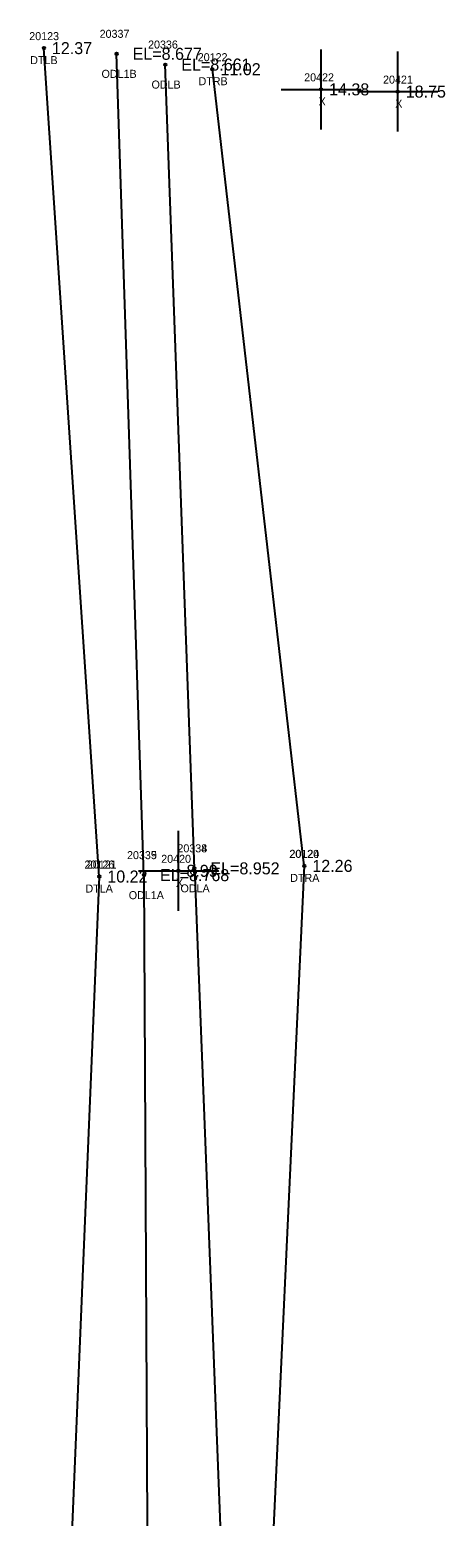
# Model space of a CAD drawing. Extents: x 2072302 to 2072980, y 127650 to 129736.
# Drawn here: x 2072396.7 to 2072448.6, y 129394 to 129579.7 of the extents above; entities that cross this region are included whole.
import ezdxf

# ---------------------------------------------------------------- set-up
doc = ezdxf.new("R2010")
doc.units = 0
for name, color, linetype in [('RD_EX_H2O', 7, 'Continuous'), ('RD_EX_H2O_txCode', 7, 'Continuous'), ('RD_EX_Misc', 7, 'Continuous'), ('RD_EX_Misc_txCode', 7, 'Continuous'), ('RD_EX_TX_H2O_ELEV', 7, 'Continuous'), ('RD_EX_TX_Misc_ELEV', 7, 'Continuous'), ('RD_SMD_Locator', 7, 'Continuous')]:
    doc.layers.add(name, color=color, linetype=linetype)

msp = doc.modelspace()

# ---------------------------------------------------------------- linework, layer by layer
at = {"layer": 'RD_EX_H2O'}
for p, q in [((2072405.39, 129473.9), (2072398.47, 129577.4)), ((2072410.97, 129474.07), (2072407.55, 129576.69)), ((2072417.26, 129474.92), (2072413.63, 129575.35)), ((2072430.99, 129475.23), (2072419.52, 129574.77))]:
    msp.add_line(p, q, dxfattribs=at)
for points in [[(2072405.39, 129473.9), (2072401.06, 129369.87), (2072405.35, 129295.82), (2072402.29, 129156.96), (2072397.22, 129166.67)], [(2072410.97, 129474.07), (2072411.5, 129368.59), (2072410.34, 129295.43), (2072404.84, 129152.23), (2072403.87, 129055.61)], [(2072417.26, 129474.92), (2072421.43, 129368.24), (2072414.98, 129295), (2072413.35, 129153), (2072411.79, 129056.82)], [(2072430.99, 129475.23), (2072426.01, 129368.3), (2072422.66, 129295.95), (2072416.7, 129153.3), (2072414.39, 129056.34)]]:
    msp.add_lwpolyline(points, dxfattribs=at)
at = {"layer": 'RD_EX_Misc'}
for p, q in [((2072433.08, 129567.25), (2072433.08, 129577.25)), ((2072442.65, 129566.97), (2072442.65, 129576.97)), ((2072428.08, 129572.25), (2072438.08, 129572.25)), ((2072437.65, 129571.97), (2072447.65, 129571.97)), ((2072415.27, 129469.61), (2072415.27, 129479.61)), ((2072410.27, 129474.61), (2072420.27, 129474.61))]:
    msp.add_line(p, q, dxfattribs=at)
at = {"layer": 'RD_SMD_Locator'}
for centre in [(2072398.47, 129577.4), (2072407.55, 129576.69), (2072413.63, 129575.35), (2072419.52, 129574.77), (2072433.08, 129572.25), (2072442.65, 129571.97), (2072405.39, 129473.9), (2072405.39, 129473.9), (2072410.97, 129474.07), (2072410.97, 129474.07), (2072415.27, 129474.61), (2072417.26, 129474.92), (2072417.26, 129474.92), (2072430.99, 129475.23), (2072430.99, 129475.23)]:
    msp.add_circle(centre, 0.15, dxfattribs=at)

# ---------------------------------------------------------------- texts
at = {"layer": 'RD_EX_H2O_txCode'}
for s, p in [('20337', (2072405.43, 129578.69)), ('20123', (2072396.64, 129578.4)), ('20336', (2072411.48, 129577.35)), ('DTLB', (2072396.76, 129575.4)), ('20122', (2072417.68, 129575.77)), ('ODL1B', (2072405.67, 129573.69)), ('ODLB', (2072411.91, 129572.35)), ('DTRB', (2072417.78, 129572.77)), ('20334', (2072415.14, 129476.92)), ('20338', (2072415.14, 129476.92)), ('20126', (2072403.54, 129474.9)), ('20121', (2072403.84, 129474.9)), ('20335', (2072408.85, 129476.07)), ('20339', (2072408.85, 129476.07)), ('20120', (2072429.11, 129476.23)), ('20124', (2072429.15, 129476.23)), ('DTRA', (2072429.23, 129473.23)), ('DTRA', (2072429.23, 129473.23)), ('DTLA', (2072403.66, 129471.9)), ('DTLA', (2072403.66, 129471.9)), ('ODL1A', (2072409.07, 129471.07)), ('ODL1A', (2072409.07, 129471.07)), ('ODLA', (2072415.53, 129471.92)), ('ODLA', (2072415.53, 129471.92))]:
    msp.add_text(s, height=1, dxfattribs=at).set_placement(p)
at = {"layer": 'RD_EX_Misc_txCode'}
for s, p in [('20422', (2072430.97, 129573.25)), ('20421', (2072440.82, 129572.97)), ('X', (2072432.77, 129570.25)), ('X', (2072442.34, 129569.97)), ('20420', (2072413.12, 129475.61)), ('X', (2072414.96, 129472.61))]:
    msp.add_text(s, height=1, dxfattribs=at).set_placement(p)
at = {"layer": 'RD_EX_TX_H2O_ELEV'}
for s, p in [('12.37', (2072399.47, 129576.65)), ('EL=8.677', (2072409.55, 129575.94)), ('EL=8.661', (2072415.63, 129574.6)), ('11.02', (2072420.52, 129574.02)), ('EL=8.952', (2072419.26, 129474.17)), ('EL=8.952', (2072419.26, 129474.17)), ('12.26', (2072431.99, 129474.48)), ('12.26', (2072431.99, 129474.48)), ('10.22', (2072406.39, 129473.15)), ('10.22', (2072406.39, 129473.15)), ('EL=8.768', (2072412.97, 129473.32)), ('EL=8.768', (2072412.97, 129473.32))]:
    msp.add_text(s, height=1.5, dxfattribs=at).set_placement(p)
at = {"layer": 'RD_EX_TX_Misc_ELEV'}
for s, p in [('14.38', (2072434.08, 129571.5)), ('18.75', (2072443.65, 129571.22)), ('8.99', (2072416.27, 129473.86))]:
    msp.add_text(s, height=1.5, dxfattribs=at).set_placement(p)

doc.saveas('drawing.dxf')
